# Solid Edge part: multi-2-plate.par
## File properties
Author: Deepak Maini
Template: normal.par
Last saved by: CADCIM
Revision: 5
Application: Solid Edge
Accuracy: 0.99
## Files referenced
..\multi-cutout.asm
6C:\solid-edge-14\c09-sldedg-14-032504\multi-cutout.asm
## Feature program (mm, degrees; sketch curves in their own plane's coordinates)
sketch for "unnamed Protrusion 1" plane through (0, 0, 0) normal (0, 0, 1) x-axis (1, 0, 0)
  line (-46.224, -15.84) -> (-46.224, 16.704)
  line (-46.224, 16.704) -> (47.664, 16.704)
  line (47.664, 16.704) -> (47.664, -15.84)
  line (47.664, -15.84) -> (-46.224, -15.84)
extrude "unnamed Protrusion 1" add finite 10.6 along +normal
extrude "unnamed Cutout 1" cut through
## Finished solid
Body 1: solid body, 7 faces, 14 edges, 8 vertices.
  Faces by surface: plane 6, cylinder 1
  Edges by curve: line 12, circle 2
Bounding box of the edges (mm): 93.888 x 32.544 x 10.600, from (-46.224, -15.84, 0) to (47.664, 16.704, 10.6).
Cylindrical faces by radius (mm): R9.0308 x1
Planar faces by outward normal: +x 1, +y 1, +z 1, -x 1, -y 1, -z 1
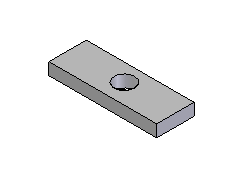
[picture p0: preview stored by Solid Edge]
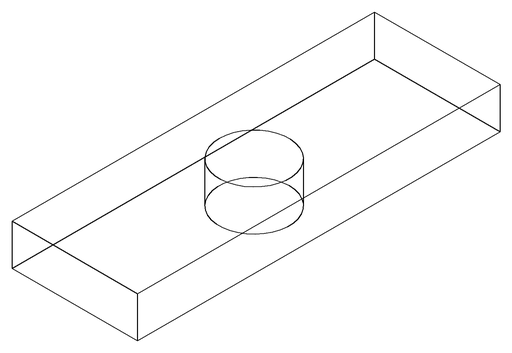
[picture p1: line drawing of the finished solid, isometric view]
